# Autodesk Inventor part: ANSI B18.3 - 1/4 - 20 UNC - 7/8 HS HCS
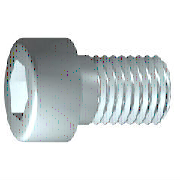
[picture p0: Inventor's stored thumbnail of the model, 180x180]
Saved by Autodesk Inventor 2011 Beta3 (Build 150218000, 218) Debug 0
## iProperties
IsCustomPart: 0
Created: 2008-01
Part Number: ANSI B18.3 - 1/4 - 20 UNC - 7/8 HS HCS
Material: Steel, Mild
Description: Hexagon Socket Head Cap Screw
Document SubType Name: Modeling
Standard: ANSI B18.3
Designer: latalom
Standard Revision: 2003
Standards Organization: ANSI
Language: en-US
Size Designation: 1/4 - 20 UNC - 7/8
Categories: <MemberInstance><Categories><Category DisplayName="Fasteners" InternalName="e4da775c-781d-43d5-af7c-5136215cf5a6" Mnemonic="FSTN"><Category DisplayName="Bolts"
Density: 7.86 g/cm^3
Mass: 8.45886 g
Surface Area: 8.12272 cm^2
Volume: 1.07619 cm^3
Author: latalom
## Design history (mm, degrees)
body "Solid1"
workplane "Work Plane1"
fillet "Fillet2" dims "d30" = 0.1778 (= R)
revolve "Body" stored, may be unused: angle "d10" = 90 deg
sketch "Sketch2"
  geometry: L1 (0, -6.668)-(0, 6.668) reference; L2 (-6.668, 0)-(6.668, 0) reference; L3 (2.757, 0)-(1.378, -2.388); L4 (1.378, -2.388)-(-1.378, -2.388); L5 (-1.378, -2.388)-(-2.757, 0); L6 (-2.757, 0)-(-1.378, 2.388); L7 (-1.378, 2.388)-(1.378, 2.388); L8 (1.378, 2.388)-(2.757, 0); 2 further points
  constraints: 12 end point, 1 coincident, 1 horizontal alignment, 1 point on line, 12 other
extrude "Slot" join sketch "Sketch2" stored distance "d11" = 10; taper "d12" = 0 deg
fillet "Fillet1" dims "d17" = 0.635 (= RR)
feature "Thread" dims "d13" = 19.0498 (= GEL), "d14" = 0
chamfer "Chamfer1" distance "d15" = 0.75565 (= -0.5 x SPD + 0.5 x GD); stored, may be unused: second distance "d16" = 0.75565 (= GUL), angle "d27" = 45 deg
sketch "Sketch1"
  geometry: L1 (-1.71, 0)-(22.225, 0); L2 (22.225, 0)-(22.225, 3.175); L3 (22.225, 3.175)-(3.175, 3.175); L4 (3.175, 3.175)-(0, 3.175); L5 (0, 3.175)-(0, 3.175); L6 (0, 3.175)-(0, 4.763); L7 (0, 4.763)-(-6.35, 4.763); L8 (-6.35, 4.763)-(-6.35, 2.757); L9 (-6.35, 2.757)-(-3.302, 2.757); L10 (-3.302, 2.757)-(-1.71, 0); L11 (-12.065, 0)-(27.94, 0) reference; L12 (0, -0.953)-(0, 5.715) reference; L13 (3.175, 3.175)-(0, 3.175)
  constraints: 22 end point, 6 parallel, 2 collinear, 2 perpendicular, 1 horizontal, 1 point on line
  dimensions: "d1" = 19.0498 distance from line of L3.end L2 (= GEL); "d2" = 3.1751 distance of L4.end L3.end (computed from GAL); "d3" = 6.35 distance between parallel lines of L8 L6 (= KOH); "d4" = 3.048 distance of L8.end L9.end (= INTI); "d5" = 60 deg angle of L10 L1; "d6" = 6.35 diameter of L3 L1 (= GD); "d7" = 6.35 diameter of L5 L1 (= BDM); "d8" = 5.51393 diameter of L9 L1 (= 1.1547 x SW); "d9" = 9.525 diameter of L7 L1 (= KOD); "d26" = 22.225 distance between parallel lines of L12 L2 (= NLG)
other parameters: "GD" = 6.35 (= KOH) [user parameter; used in 2 equation terms], "NLG" = 22.225 [user parameter; used in 1 equation term], "GEL" = 19.0498 [user parameter; used in 2 equation terms], "KOD" = 9.525 [user parameter; used in 1 equation term], "KOH" = 6.35 [user parameter; used in 3 equation terms], "INTI" = 3.048 [user parameter; used in 1 equation term], "GAL" = 3.175 [user parameter; used in 1 equation term], "GUL" = 0.75565 [user parameter; used in 1 equation term], "BDM" = 6.35 (= KOH) [user parameter; used in 1 equation term], "SW" = 4.7752 [user parameter; used in 2 equation terms], "RR" = 0.635 [user parameter; used in 1 equation term], "SPD" = 4.8387 [user parameter; used in 2 equation terms], "d19" = 0, "d28" = 0, "d29" = 0, "R" = 0.1778 [user parameter; used in 1 equation term], "PHH" = 0.2032 [user parameter], "GD1" = 4.8387 (= SPD) [user parameter], "THREADDIA" = 6.35 [user parameter], "FAWI" = 45 deg [user parameter], "PTC" = 1.27 (computed from TPU) [user parameter], "KOH1" = 5.715 [user parameter], "NND" = 6.35 [user parameter], "TOA" = 30 deg [user parameter], "E0" = 5.51536 (= 1.155 x SW) [user parameter]
